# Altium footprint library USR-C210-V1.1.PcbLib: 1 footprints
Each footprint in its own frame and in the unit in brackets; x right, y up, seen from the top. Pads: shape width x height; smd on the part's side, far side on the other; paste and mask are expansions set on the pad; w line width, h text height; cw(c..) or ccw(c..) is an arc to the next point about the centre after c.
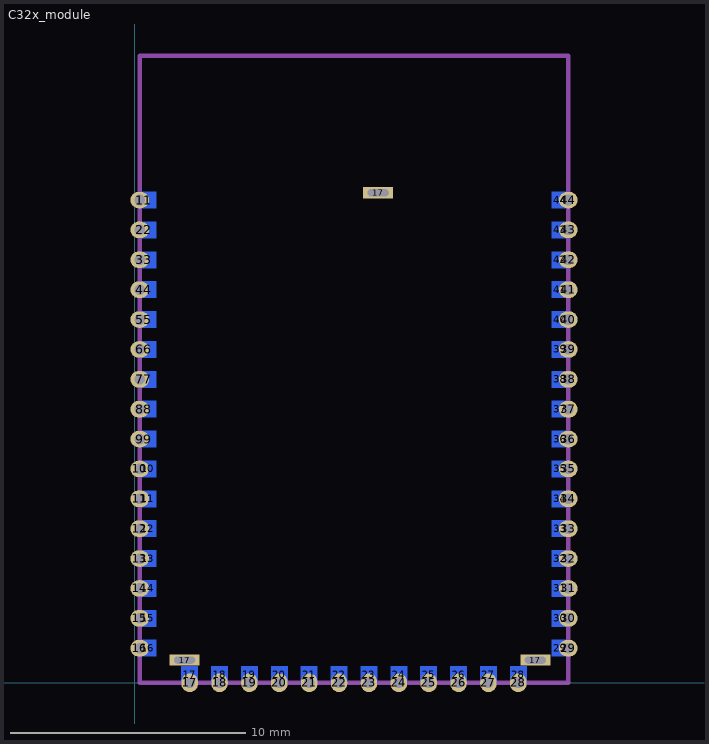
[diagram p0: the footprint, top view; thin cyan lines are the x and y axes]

## C32x_module [mm]
height 1.1
pads (91):
  oval 0.8x0.7 hole 0.45: 1(0.2,20.52) 2(0.2,19.25) 3(0.2,17.98) 4(0.2,16.71) 5(0.2,15.44) 6(0.2,14.17) 7(0.2,12.9) 8(0.2,11.63) 9(0.2,10.36) 10(0.2,9.09) 11(0.2,7.82) 12(0.2,6.55) 13(0.2,5.28) 14(0.2,4.01) 15(0.2,2.74) 16(0.2,1.47) 29(18.42,1.47) 30(18.42,2.74) 31(18.42,4.01) 32(18.42,5.28) 33(18.42,6.55) 34(18.42,7.82) 35(18.42,9.09) 36(18.42,10.36) 37(18.42,11.63) 38(18.42,12.9) 39(18.42,14.17) 40(18.42,15.44) 41(18.42,16.71) 42(18.42,17.98) 43(18.42,19.25) 44(18.42,20.52)
  rect 0.7x0.7 smd far side: 1(0.55,20.52) 2(0.55,19.25) 3(0.55,17.98) 4(0.55,16.71) 5(0.55,15.44) 6(0.55,14.17) 7(0.55,12.9) 8(0.55,11.63) 9(0.55,10.36) 10(0.55,9.09) 11(0.55,7.82) 12(0.55,6.55) 13(0.55,5.28) 14(0.55,4.01) 15(0.55,2.74) 16(0.55,1.47) 17(2.325,0.35) 18(3.595,0.35) 19(4.865,0.35) 20(6.135,0.35) 21(7.405,0.35) 22(8.675,0.35) 23(9.945,0.35) 24(11.215,0.35) 25(12.485,0.35) 26(13.755,0.35) 27(15.025,0.35) 28(16.295,0.35) 29(18.07,1.47) 30(18.07,2.74) 31(18.07,4.01) 32(18.07,5.28) 33(18.07,6.55) 34(18.07,7.82) 35(18.07,9.09) 36(18.07,10.36) 37(18.07,11.63) 38(18.07,12.9) 39(18.07,14.17) 40(18.07,15.44) 41(18.07,16.71) 42(18.07,17.98) 43(18.07,19.25) 44(18.07,20.52)
  rect 1.27x0.483 hole 0.3 slot 0.889 at 0 deg mask+0.051: 17(2.108,0.965) 17(10.338,20.828) 17(17.018,0.965)
  oval 0.7x0.8 hole 0.45: 17(2.325,0) 18(3.595,0) 19(4.865,0) 20(6.135,0) 21(7.405,0) 22(8.675,0) 23(9.945,0) 24(11.215,0) 25(12.485,0) 26(13.755,0) 27(15.025,0) 28(16.295,0)
Mechanical 1:
  lines w0.2: 0.2,0 18.42,0 18.42,26.65 0.2,26.65 0.2,0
